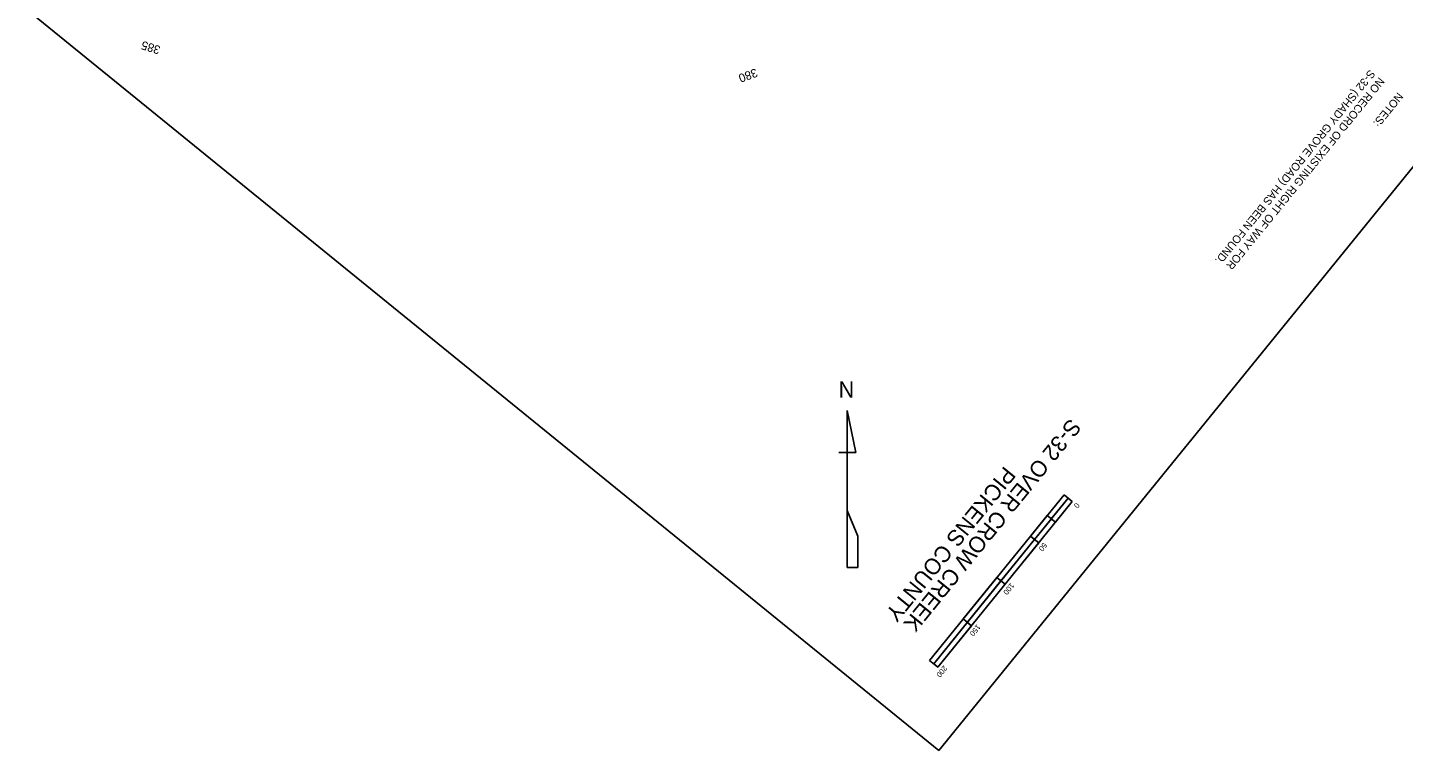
# Model space of a CAD drawing. Extents: x 144 to 1452322, y 4017 to 1128039.
# Drawn here: x 1449766 to 1451055, y 1125948 to 1126625 of the extents above; entities that cross this region are included whole.
import ezdxf

# ---------------------------------------------------------------- set-up
doc = ezdxf.new("R2010")
doc.units = 0
for name, color, linetype in [('RD_HC_Data', 7, 'Continuous'), ('RD_HC_TX_Sta50', 7, 'Continuous'), ('RD_SHT_ShtClip', 7, 'Continuous'), ('RD_SHT_TX', 7, 'Continuous')]:
    doc.layers.add(name, color=color, linetype=linetype)

msp = doc.modelspace()

# ---------------------------------------------------------------- linework, layer by layer
at = {"layer": 'RD_SHT_ShtClip'}
for p, q in [((1451754.4, 1127345), (1450619.6, 1125947.8)), ((1450619.6, 1125947.8), (1449765.8, 1126641.3))]:
    msp.add_line(p, q, dxfattribs=at)
at = {"layer": 'RD_SHT_TX'}
for p, q in [((1450541.7, 1126227.1), (1450533.8, 1126266.3)), ((1450533.8, 1126266.3), (1450533.8, 1126266.3)), ((1450533.8, 1126266.3), (1450533.8, 1126227.1)), ((1450526, 1126227.1), (1450533.8, 1126227.1)), ((1450533.8, 1126172.7), (1450533.8, 1126227.1)), ((1450533.8, 1126227.1), (1450541.7, 1126227.1)), ((1450541.7, 1126227.1), (1450541.7, 1126227.5)), ((1450736.9, 1126187.4), (1450610.8, 1126032.2)), ((1450744.6, 1126181.1), (1450736.9, 1126187.4)), ((1450744.6, 1126181.1), (1450618.6, 1126025.9)), ((1450740.7, 1126184.2), (1450709.2, 1126145.4)), ((1450543.6, 1126148.7), (1450533.8, 1126172.7)), ((1450533.8, 1126172.7), (1450533.8, 1126119.3)), ((1450728.9, 1126161.7), (1450721.1, 1126168)), ((1450543.6, 1126119.3), (1450543.6, 1126149)), ((1450543.6, 1126149), (1450543.6, 1126148.7)), ((1450713.1, 1126142.3), (1450705.3, 1126148.6)), ((1450705.3, 1126148.6), (1450705.3, 1126148.6)), ((1450709.2, 1126145.4), (1450614.7, 1126029)), ((1450533.8, 1126119.3), (1450543.6, 1126119.3)), ((1450681.6, 1126103.5), (1450673.8, 1126109.8)), ((1450650.1, 1126064.7), (1450642.3, 1126071)), ((1450642.3, 1126071), (1450642.3, 1126071)), ((1450618.6, 1126025.9), (1450610.8, 1126032.2)), ((1450611.6, 1126031.5), (1450611.6, 1126031.5)), ((1450612.4, 1126030.9), (1450612.4, 1126030.9)), ((1450613.1, 1126030.3), (1450613.1, 1126030.3)), ((1450613.9, 1126029.6), (1450613.9, 1126029.6))]:
    msp.add_line(p, q, dxfattribs=at)
for points in [[(1450744.6, 1126181.1), (1450728.9, 1126161.7), (1450724.9, 1126164.9), (1450740.7, 1126184.3)], [(1450725, 1126164.8), (1450709.2, 1126145.4), (1450705.3, 1126148.6), (1450721.1, 1126168)], [(1450713.1, 1126142.3), (1450681.5, 1126103.4), (1450677.7, 1126106.6), (1450709.2, 1126145.4)], [(1450677.7, 1126106.6), (1450646.2, 1126067.8), (1450642.3, 1126071), (1450673.8, 1126109.8)], [(1450650.1, 1126064.7), (1450618.6, 1126025.9), (1450614.7, 1126029), (1450646.2, 1126067.8)]]:
    msp.add_lwpolyline(points, close=True, dxfattribs=at)

# ---------------------------------------------------------------- texts
at = {"layer": 'RD_HC_Data'}
for s, p in [('S-32 (SHADY GROVE ROAD) HAS BEEN FOUND.', (1451023.2, 1126586.2)), ('NO RECORD OF EXISTING RIGHT OF WAY FOR', (1451031.9, 1126579.1)), ('NOTES:', (1451049.4, 1126564.9))]:
    msp.add_text(s, height=7.5, rotation=230.9167, dxfattribs=at).set_placement(p)
at = {"layer": 'RD_HC_TX_Sta50'}
for s, rotation, p in [('385', 162.6604, (1449890.9, 1126607.4)), ('380', 200.2376, (1450447.9, 1126587))]:
    msp.add_text(s, height=8, rotation=rotation, dxfattribs=at).set_placement(p)
at = {"layer": 'RD_SHT_TX'}
for s, height, rotation, p in [('N', 15, 360, (1450525.7, 1126278.5)), ('S-32 OVER CROW CREEK', 15, 230.9167, (1450742.4, 1126259.8)), ('PICKENS COUNTY', 15, 230.9167, (1450681, 1126215)), ('0', 5, 230.9132, (1450748, 1126180.4)), ('50', 5, 230.9167, (1450717.6, 1126143)), ('100', 5, 230.914, (1450686.8, 1126105.2)), ('150', 5, 230.9127, (1450655.3, 1126066.4)), ('200', 5, 230.9159, (1450624.1, 1126027.9))]:
    msp.add_text(s, height=height, rotation=rotation, dxfattribs=at).set_placement(p)

doc.saveas('drawing.dxf')
